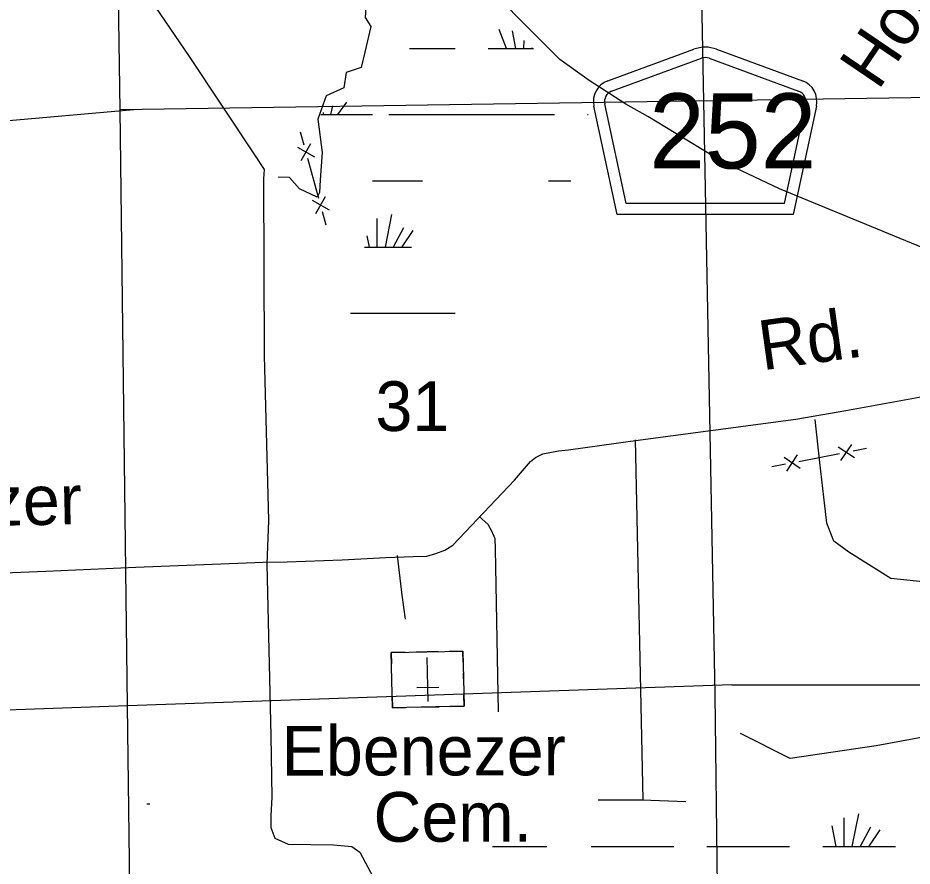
# Model space of a CAD drawing. Extents: x 2480962 to 2688785, y 277103 to 599240.
# Drawn here: x 2581065 to 2589173, y 400819 to 408503 of the extents above; entities that cross this region are included whole.
import ezdxf

# ---------------------------------------------------------------- set-up
doc = ezdxf.new("R2010")
doc.units = 0
for name, color, linetype in [('County Routes Highway Center Lines', 7, 'Continuous'), ('Culture', 7, 'Continuous'), ('Culture Text', 7, 'Continuous'), ('Local Roads Improved', 7, 'Continuous'), ('Local Roads Paved', 7, 'Continuous'), ('Local Roads Related Text', 7, 'Continuous'), ('Roadshields County Roads', 7, 'Continuous'), ('Section Lines', 7, 'Continuous'), ('Section Numbers', 7, 'Continuous'), ('Swamps', 7, 'Continuous'), ('Township and Range lines', 7, 'Continuous'), ('Uninventoried Roads and Features', 7, 'Continuous')]:
    doc.layers.add(name, color=color, linetype=linetype)

msp = doc.modelspace()

# ---------------------------------------------------------------- linework, layer by layer
at = {"layer": 'County Routes Highway Center Lines'}
msp.add_lwpolyline([(2589373.684, 406378.793), (2587971.507, 406954.423), (2587454.915, 407197.96), (2586775.966, 407611.233), (2586576.709, 407721.931), (2586244.614, 407935.948), (2585978.938, 408127.825), (2585632.084, 408474.679), (2584820.297, 409301.226)], dxfattribs=at)
at = {"layer": 'Culture'}
for p, q in [((2584575.596, 402755.424), (2584450.625, 402752.764)), ((2584450.625, 402752.764), (2584452.753, 402652.786)), ((2584875.528, 402761.81), (2584675.574, 402757.553)), ((2584785.13, 402309.784), (2584776.615, 402709.693)), ((2585100.477, 402766.599), (2584975.506, 402763.939)), ((2585102.606, 402666.622), (2585100.477, 402766.599)), ((2584457.01, 402452.832), (2584454.882, 402552.809)), ((2585106.863, 402466.667), (2585104.735, 402566.645)), ((2584882.446, 402436.884), (2584682.491, 402432.627)), ((2584459.139, 402352.854), (2584461.267, 402252.877)), ((2585111.12, 402266.713), (2585108.992, 402366.69)), ((2584461.267, 402252.877), (2584586.239, 402255.538)), ((2584686.216, 402257.666), (2584886.171, 402261.923)), ((2584986.148, 402264.052), (2585111.12, 402266.713))]:
    msp.add_line(p, q, dxfattribs=at)
msp.add_lwpolyline([(2585111.12, 402266.713), (2584461.267, 402252.877), (2584450.625, 402752.764), (2585100.477, 402766.599)], close=True, dxfattribs=at)
at = {"layer": 'Local Roads Improved'}
msp.add_lwpolyline([(2582222.148, 408736.538), (2582618.513, 408153.208), (2583209.322, 407263.255), (2583299.066, 407128.64), (2583291.587, 407046.376), (2583299.066, 405445.956), (2583336.459, 403950.237), (2583321.501, 403553.871), (2583358.894, 401998.323), (2583366.373, 401444.907), (2583358.894, 401272.899), (2583358.894, 401168.199), (2583396.287, 401070.977), (2583515.945, 401018.627), (2583927.268, 401011.148), (2584091.797, 400996.191), (2584166.583, 400943.841), (2584286.24, 400719.483)], dxfattribs=at)
at = {"layer": 'Local Roads Paved'}
msp.add_line((2586661.811, 404680.84), (2586729.918, 401417.883), dxfattribs=at)
for points in [[(2580941.905, 403475.731), (2581320.124, 403491.941), (2582133.295, 403527.061), (2583289.564, 403572.988), (2583505.689, 403575.689), (2584005.479, 403594.6), (2584402.609, 403613.511), (2584648.451, 403624.317), (2584772.723, 403627.019), (2584853.77, 403651.333), (2584934.817, 403681.05), (2585007.759, 403726.977), (2585566.983, 404315.918), (2585712.867, 404483.415), (2585758.794, 404521.237), (2585823.631, 404553.655), (2585966.814, 404580.671), (2586055.966, 404588.776), (2586617.891, 404669.823), (2588117.259, 404867.037), (2588571.122, 404945.382), (2589270.827, 405072.356)], [(2585247.037, 403987.384), (2585324.432, 403916.181), (2585358.485, 403857.361), (2585389.443, 403786.158), (2585392.539, 403693.285), (2585420.401, 402216.596)], [(2584504.049, 403631.369), (2584547.39, 403272.258), (2584575.252, 403055.553)], [(2586327.466, 401417.883), (2586723.726, 401417.883), (2587119.987, 401405.5)]]:
    msp.add_lwpolyline(points, dxfattribs=at)
at = {"layer": 'Roadshields County Roads'}
for p, q in [((2586414.033, 407933.041), (2587193.408, 408219.378)), ((2587400.32, 408219.379), (2588178.342, 407933.539)), ((2586448.518, 407839.176), (2587262.378, 408138.182)), ((2587331.35, 408138.182), (2588143.858, 407839.672)), ((2586578.839, 406821.216), (2586385.226, 407724.348)), ((2588207.15, 407724.845), (2588013.431, 406821.216)), ((2586498.005, 406721.215), (2586287.447, 407703.387)), ((2588304.928, 407703.885), (2588094.264, 406721.216)), ((2588013.43, 406821.216), (2586578.838, 406821.216)), ((2588094.264, 406721.216), (2586498.004, 406721.216))]:
    msp.add_line(p, q, dxfattribs=at)
for centre, radius, start, end in [((2587296.864, 407937.781), 300, 69.8269806, 110.1730139), ((2587296.864, 408044.317), 100, 69.8269876, 110.1729839), ((2586483.004, 407745.31), 200, 110.1729839, 192.0998896), ((2588109.372, 407745.807), 200, 347.9000917, 69.8270083), ((2586483.004, 407745.31), 100, 110.1729839, 192.0998896), ((2588109.372, 407745.806), 100, 347.9000932, 69.8269876)]:
    msp.add_arc(centre, radius, start, end, dxfattribs=at)
at = {"layer": 'Section Lines'}
for p, q in [((2587282.81, 407750.001), (2587187.676, 413023.299)), ((2592576.313, 407829.653), (2581991.265, 407670.378)), ((2587387.395, 402370.527), (2587282.81, 407750.001)), ((2577148.475, 407246.338), (2582116.016, 407672.255)), ((2587453.142, 397034.851), (2587387.395, 402370.527))]:
    msp.add_line(p, q, dxfattribs=at)
at = {"layer": 'Swamps'}
for p, q in [((2585494.883, 408227.343), (2585429.409, 408399.209)), ((2583964.917, 407626.632), (2584048.694, 407740.335)), ((2584429.457, 407627.141), (2585929.455, 407627.178)), ((2584320.415, 406685.692), (2584320.419, 406427.128)), ((2584453.32, 406721.942), (2584394.383, 406427.235)), ((2584562.061, 406601.121), (2584468.055, 406426.531)), ((2588553.239, 401256.075), (2588553.243, 400997.511)), ((2588686.144, 401292.325), (2588627.207, 400997.618)), ((2588444.499, 401183.578), (2588481.711, 400997.531)), ((2588794.885, 401171.504), (2588700.88, 400996.915)), ((2588879.461, 401147.341), (2588780.143, 400998.359)), ((2586262.299, 400997.453), (2587012.298, 400997.472)), ((2587312.298, 400997.479), (2587762.297, 400997.491)), ((2587762.297, 400997.491), (2588062.297, 400997.498))]:
    msp.add_line(p, q, dxfattribs=at)
for points in [[(2585579.957, 408227.256), (2585550.953, 408386.755)], [(2585650.956, 408227.208), (2585654.852, 408298.658)], [(2584614.772, 408227.151), (2585029.448, 408227.161)], [(2585329.448, 408227.168), (2585739.153, 408227.178)], [(2585727.642, 408227.388), (2585729.838, 408235.076)], [(2583835.622, 407627.146), (2583835.966, 407645.389)], [(2583902.721, 407626.938), (2583919.576, 407707.844)], [(2583811.517, 407627.126), (2584279.457, 407627.137)], [(2586229.454, 407627.185), (2586235.653, 407627.185)], [(2584279.465, 407027.132), (2584734.472, 407027.143)], [(2585874.846, 407027.171), (2586079.463, 407027.176)], [(2584228.767, 406527.743), (2584248.887, 406427.148)], [(2584646.637, 406576.958), (2584547.319, 406427.975)], [(2584207.491, 406427.125), (2584633.759, 406427.135)], [(2584080.617, 405827.116), (2585029.479, 405827.14)], [(2582235.223, 401382.965), (2582262.817, 401382.966)], [(2585369.216, 400997.43), (2585862.299, 400997.443)], [(2588362.297, 400997.506), (2589021.032, 400997.523)]]:
    msp.add_lwpolyline(points, dxfattribs=at)
at = {"layer": 'Township and Range lines'}
for p, q in [((2581991.265, 407670.378), (2581926.717, 412858.865)), ((2582058.45, 402269.854), (2581991.265, 407670.378)), ((2587537.895, 402461.945), (2582058.45, 402269.854)), ((2587537.895, 402461.945), (2592713.278, 402455.571)), ((2582058.45, 402269.854), (2576751.859, 402083.823)), ((2582124.276, 396978.608), (2582058.45, 402269.854))]:
    msp.add_line(p, q, dxfattribs=at)
at = {"layer": 'Uninventoried Roads and Features'}
for p, q in [((2583659.912, 407348.971), (2583626.407, 407469.397)), ((2583599.698, 407332.219), (2583753.63, 407245.298)), ((2583633.203, 407211.793), (2583720.125, 407365.724)), ((2583793.932, 406867.267), (2583693.417, 407228.545)), ((2583733.718, 406850.514), (2583887.65, 406763.593)), ((2583767.223, 406730.088), (2583854.145, 406884.019)), ((2583860.941, 406626.414), (2583827.437, 406746.841)), ((2588526.749, 404492.757), (2588625.742, 404639.217)), ((2588649.475, 404516.49), (2588503.015, 404615.483)), ((2588760.335, 404601.587), (2588637.609, 404577.854)), ((2588158.569, 404421.556), (2588012.109, 404520.549)), ((2588035.843, 404397.822), (2588134.836, 404544.282)), ((2588514.882, 404554.12), (2588146.703, 404482.919)), ((2588023.976, 404459.185), (2587901.25, 404435.452))]:
    msp.add_line(p, q, dxfattribs=at)
for points in [[(2584125.725, 410107.352), (2584063.852, 409926.37), (2584043.777, 409498.758), (2584073.272, 409193.894), (2584060.845, 409048.669), (2584149.922, 408942.14), (2584227.419, 408742.596), (2584214.949, 408506.512), (2584264.913, 408424.356), (2584211.842, 408191.351), (2584176.06, 408055.338), (2584041.913, 408008.274), (2584021.607, 407870.627), (2583861.009, 407795.988), (2583784.301, 407585.721), (2583825.334, 407283.014), (2583805.345, 407037.119), (2583799.995, 406922.959), (2583777.723, 406879.998), (2583619.824, 406954.262), (2583526.967, 407056.851), (2583424.581, 407060.665)], [(2590403.671, 400509.285), (2590369.708, 400657.477), (2590325.135, 400851.86), (2590404.976, 401004.192), (2590493.702, 401193.427), (2590390.559, 401419.537), (2590345.314, 401925.141), (2590143.606, 402249.862), (2590032.387, 402586.003), (2589940.749, 403001.783), (2589882.387, 403209.43), (2589657.8, 403334.596), (2589413.671, 403378.19), (2588980.286, 403425.847), (2588598.967, 403662.027), (2588463.7, 403761.86), (2588398.543, 403924.913), (2588334.968, 404476.557), (2588292.171, 404864.287)], [(2592605.366, 402407.787), (2590497.441, 402314.718), (2590298.616, 402314.728), (2590071.406, 402194.334), (2589682.314, 402061.135), (2588847.734, 401907.699), (2588066.381, 401793.957), (2587615.796, 402019.129)]]:
    msp.add_lwpolyline(points, dxfattribs=at)

# ---------------------------------------------------------------- texts
at = {"layer": 'Culture Text'}
for s, rotation, p in [('Ebenezer', 0.0670139, (2583456.848, 401639.074)), ('Cem.', 0.0670194, (2584289.188, 401039.421))]:
    msp.add_text(s, height=450, rotation=rotation, dxfattribs=at).set_placement(p)
at = {"layer": 'Local Roads Related Text'}
for s, rotation, p in [('Rd.', 7.8998194, (2587814.906, 405309.454)), ('Ebenezer', 1.234675, (2579074.443, 403862.213))]:
    msp.add_text(s, height=450, rotation=rotation, dxfattribs=at).set_placement(p)
at = {"layer": 'Roadshields County Roads'}
msp.add_text('252', height=680, dxfattribs=at).set_placement((2586788.619, 407139.499))
at = {"layer": 'Section Numbers'}
msp.add_text('31', height=450, rotation=0.02935, dxfattribs=at).set_placement((2584307.034, 404760.723))
at = {"layer": 'Uninventoried Roads and Features'}
msp.add_text('Horne', height=450, rotation=55.9122917, dxfattribs=at).set_placement((2588864.731, 407838.189))

doc.saveas('drawing.dxf')
